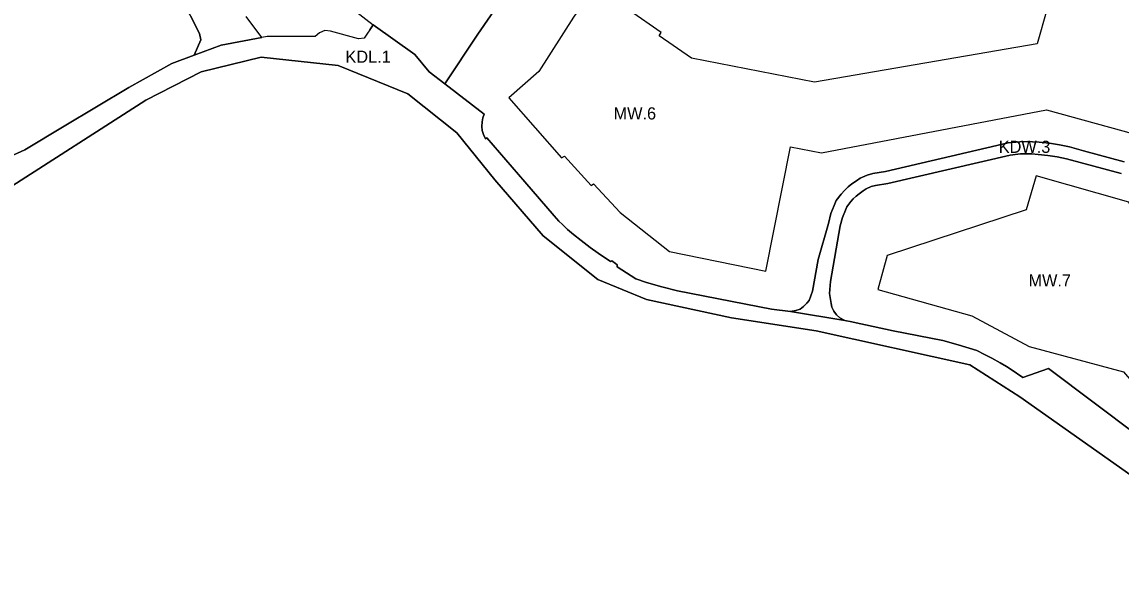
# Model space of a CAD drawing. Extents: x 7432050 to 7433361, y 5551438 to 5552391.
# Drawn here: x 7432631.9 to 7432993.3, y 5551479.7 to 5551658.9 of the extents above; entities that cross this region are included whole.
import ezdxf

# ---------------------------------------------------------------- set-up
doc = ezdxf.new("R2010")
doc.units = 0
for name, color, linetype in [('granica planu', 7, 'Continuous'), ('linie rozgraniczające', 7, 'Continuous'), ('nieprzekraczalne linie zabudowy', 7, 'Continuous'), ('oznaczenia przeznaczen', 7, 'Continuous')]:
    doc.layers.add(name, color=color, linetype=linetype)

msp = doc.modelspace()

# ---------------------------------------------------------------- linework, layer by layer
at = {"layer": 'granica planu'}
msp.add_line((7432710.59, 5551647.34), (7432690.81, 5551642.54), dxfattribs=at)
for points in [[(7432774.93, 5551622.43), (7432758.81, 5551635.29), (7432735.85, 5551644.65), (7432710.59, 5551647.34)], [(7432690.81, 5551642.54), (7432672.61, 5551633.22), (7432625.82, 5551603.17)], [(7432893.1, 5551557.41), (7432865.21, 5551561.71), (7432837.26, 5551567.72), (7432821.27, 5551574.22), (7432803.26, 5551588.64), (7432787.38, 5551607.01), (7432774.93, 5551622.43)], [(7433039.39, 5551479.73), (7432960, 5551535.68), (7432943.56, 5551546.17), (7432893.1, 5551557.41)]]:
    msp.add_lwpolyline(points, dxfattribs=at)
at = {"layer": 'linie rozgraniczające'}
for p, q in [((7432718.68, 5551680.18), (7432747.44, 5551658.04)), ((7432690.3, 5551655.18), (7432682.77, 5551670.1)), ((7432682.77, 5551670.1), (7432690.3, 5551655.18)), ((7432781.82, 5551654.95), (7432793.64, 5551672.05)), ((7432793.64, 5551672.05), (7432781.82, 5551654.95)), ((7432710.81, 5551653.82), (7432705.68, 5551660.68)), ((7432747.44, 5551658.04), (7432746.3, 5551656.38)), ((7432746.3, 5551656.38), (7432747.44, 5551658.04)), ((7432747.44, 5551658.04), (7432761.05, 5551648.27)), ((7432690.73, 5551653.11), (7432690.3, 5551655.18)), ((7432690.3, 5551655.18), (7432690.73, 5551653.11)), ((7432729.77, 5551655.4), (7432728.29, 5551654.19)), ((7432731.46, 5551656.08), (7432729.77, 5551655.4)), ((7432733.37, 5551655.91), (7432731.46, 5551656.08)), ((7432742.59, 5551653.39), (7432733.37, 5551655.91)), ((7432770.95, 5551638.61), (7432781.82, 5551654.95)), ((7432781.82, 5551654.95), (7432770.95, 5551638.61)), ((7432688.55, 5551648), (7432690.73, 5551653.11)), ((7432690.73, 5551653.11), (7432688.55, 5551648)), ((7432688.55, 5551648), (7432697.48, 5551651.33)), ((7432697.48, 5551651.33), (7432688.55, 5551648)), ((7432697.48, 5551651.33), (7432710.81, 5551653.82)), ((7432727.9, 5551654.19), (7432712.5, 5551654.14)), ((7432728.29, 5551654.19), (7432727.9, 5551654.19)), ((7432744.43, 5551653.65), (7432742.59, 5551653.39)), ((7432681.19, 5551645.26), (7432688.55, 5551648)), ((7432688.55, 5551648), (7432681.19, 5551645.26)), ((7432690.81, 5551642.54), (7432710.59, 5551647.34)), ((7432710.59, 5551647.34), (7432690.81, 5551642.54)), ((7432710.59, 5551647.34), (7432735.85, 5551644.65)), ((7432761.05, 5551648.27), (7432765.76, 5551642.57)), ((7432667.11, 5551637.34), (7432681.19, 5551645.26)), ((7432735.85, 5551644.65), (7432758.81, 5551635.29)), ((7432672.61, 5551633.22), (7432690.81, 5551642.54)), ((7432765.76, 5551642.57), (7432770.95, 5551638.61)), ((7432645.84, 5551624.65), (7432667.11, 5551637.34)), ((7432625.82, 5551603.17), (7432672.61, 5551633.22)), ((7432758.81, 5551635.29), (7432774.93, 5551622.43)), ((7432774.93, 5551622.43), (7432787.38, 5551607.01)), ((7432783.67, 5551621.94), (7432784.29, 5551620.49)), ((7432784.29, 5551620.49), (7432783.67, 5551621.94)), ((7432784.29, 5551620.49), (7432784.8, 5551620.82)), ((7432784.8, 5551620.82), (7432784.29, 5551620.49)), ((7432784.8, 5551620.82), (7432797.25, 5551606.4)), ((7432797.25, 5551606.4), (7432784.8, 5551620.82)), ((7432966.39, 5551619.39), (7432964.19, 5551619.57)), ((7432976.35, 5551617.83), (7432973.03, 5551618.54)), ((7432949.18, 5551617.52), (7432915.83, 5551609.78)), ((7432956.82, 5551615.19), (7432916.62, 5551605.86)), ((7432916.62, 5551605.86), (7432956.82, 5551615.19)), ((7432960.22, 5551615.53), (7432956.82, 5551615.19)), ((7432956.82, 5551615.19), (7432960.22, 5551615.53)), ((7432962.4, 5551615.6), (7432960.22, 5551615.53)), ((7432960.22, 5551615.53), (7432962.4, 5551615.6)), ((7432963.98, 5551615.57), (7432962.4, 5551615.6)), ((7432962.4, 5551615.6), (7432963.98, 5551615.57)), ((7432966.02, 5551615.4), (7432963.98, 5551615.57)), ((7432963.98, 5551615.57), (7432966.02, 5551615.4)), ((7432969.23, 5551615.07), (7432966.02, 5551615.4)), ((7432966.02, 5551615.4), (7432969.23, 5551615.07)), ((7432972.31, 5551614.61), (7432969.23, 5551615.07)), ((7432969.23, 5551615.07), (7432972.31, 5551614.61)), ((7432975.4, 5551613.94), (7432972.31, 5551614.61)), ((7432972.31, 5551614.61), (7432975.4, 5551613.94)), ((7432980.9, 5551616.6), (7432976.35, 5551617.83)), ((7432994.34, 5551612.91), (7432980.9, 5551616.6)), ((7432979.85, 5551612.74), (7432975.4, 5551613.94)), ((7432975.4, 5551613.94), (7432979.85, 5551612.74)), ((7432993.28, 5551609.06), (7432979.85, 5551612.74)), ((7432979.85, 5551612.74), (7432993.28, 5551609.06)), ((7432907.55, 5551607.55), (7432906.3, 5551606.7)), ((7432909.78, 5551608.57), (7432907.55, 5551607.55)), ((7432911.68, 5551609.06), (7432909.78, 5551608.57)), ((7432915.83, 5551609.78), (7432911.68, 5551609.06)), ((7432787.38, 5551607.01), (7432803.26, 5551588.64)), ((7432797.25, 5551606.4), (7432806.89, 5551595.14)), ((7432806.89, 5551595.14), (7432797.25, 5551606.4)), ((7432909.53, 5551604.05), (7432908.55, 5551603.39)), ((7432908.55, 5551603.39), (7432909.53, 5551604.05)), ((7432911.13, 5551604.79), (7432909.53, 5551604.05)), ((7432909.53, 5551604.05), (7432911.13, 5551604.79)), ((7432912.53, 5551605.15), (7432911.13, 5551604.79)), ((7432911.13, 5551604.79), (7432912.53, 5551605.15)), ((7432916.62, 5551605.86), (7432912.53, 5551605.15)), ((7432912.53, 5551605.15), (7432916.62, 5551605.86)), ((7432901.31, 5551602.35), (7432899.67, 5551600.18)), ((7432905.21, 5551600.76), (7432904.43, 5551599.85)), ((7432904.43, 5551599.85), (7432905.21, 5551600.76)), ((7432906.18, 5551601.66), (7432905.21, 5551600.76)), ((7432905.21, 5551600.76), (7432906.18, 5551601.66)), ((7432907.16, 5551602.45), (7432906.18, 5551601.66)), ((7432906.18, 5551601.66), (7432907.16, 5551602.45)), ((7432908.55, 5551603.39), (7432907.16, 5551602.45)), ((7432907.16, 5551602.45), (7432908.55, 5551603.39)), ((7432902.64, 5551597.04), (7432901.67, 5551594.67)), ((7432901.67, 5551594.67), (7432902.64, 5551597.04)), ((7432903.13, 5551598.12), (7432902.64, 5551597.04)), ((7432902.64, 5551597.04), (7432903.13, 5551598.12)), ((7432904.43, 5551599.85), (7432903.13, 5551598.12)), ((7432903.13, 5551598.12), (7432904.43, 5551599.85)), ((7432897.85, 5551595.92), (7432897.06, 5551592.7)), ((7432901.67, 5551594.67), (7432900.98, 5551591.88)), ((7432900.98, 5551591.88), (7432901.67, 5551594.67)), ((7432897.06, 5551592.7), (7432893.69, 5551580.78)), ((7432900.98, 5551591.88), (7432897.71, 5551573.62)), ((7432897.71, 5551573.62), (7432900.98, 5551591.88)), ((7432803.26, 5551588.64), (7432821.27, 5551574.22)), ((7432818.75, 5551584.81), (7432821.43, 5551582.88)), ((7432821.43, 5551582.88), (7432818.75, 5551584.81)), ((7432821.43, 5551582.88), (7432825.46, 5551580.23)), ((7432825.46, 5551580.23), (7432821.43, 5551582.88)), ((7432827.03, 5551579.49), (7432827.61, 5551579.04)), ((7432827.61, 5551579.04), (7432827.03, 5551579.49)), ((7432821.27, 5551574.22), (7432837.26, 5551567.72)), ((7432833.8, 5551574.53), (7432837.32, 5551573.28)), ((7432837.32, 5551573.28), (7432833.8, 5551574.53)), ((7432837.32, 5551573.28), (7432842.27, 5551571.82)), ((7432842.27, 5551571.82), (7432837.32, 5551573.28)), ((7432842.27, 5551571.82), (7432847.51, 5551570.56)), ((7432847.51, 5551570.56), (7432842.27, 5551571.82)), ((7432897.4, 5551569.62), (7432897.71, 5551573.62)), ((7432898, 5551566.33), (7432897.4, 5551569.62)), ((7432886.35, 5551564.02), (7432884.58, 5551563.76)), ((7432887.75, 5551564.47), (7432886.35, 5551564.02)), ((7432888.9, 5551565.33), (7432887.75, 5551564.47)), ((7432889.99, 5551566.48), (7432888.9, 5551565.33)), ((7432890.78, 5551567.38), (7432889.99, 5551566.48)), ((7432884.58, 5551563.76), (7432902.52, 5551560.82)), ((7432902.52, 5551560.82), (7432904.79, 5551560.32)), ((7432893.1, 5551557.41), (7432943.56, 5551546.17)), ((7432904.79, 5551560.32), (7432905.22, 5551560.23)), ((7432905.22, 5551560.23), (7432904.79, 5551560.32)), ((7432945.89, 5551550.91), (7432948.43, 5551549.61)), ((7432948.43, 5551549.61), (7432945.89, 5551550.91))]:
    msp.add_line(p, q, dxfattribs=at)
for points in [[(7432761.05, 5551648.27), (7432747.44, 5551658.04), (7432744.43, 5551653.65)], [(7432712.5, 5551654.14), (7432710.81, 5551653.82), (7432697.48, 5551651.33)], [(7432774.93, 5551622.43), (7432758.81, 5551635.29), (7432735.85, 5551644.65), (7432710.59, 5551647.34)], [(7432770.95, 5551638.61), (7432765.76, 5551642.57), (7432761.05, 5551648.27)], [(7432681.19, 5551645.26), (7432667.11, 5551637.34), (7432645.84, 5551624.65)], [(7432690.81, 5551642.54), (7432672.61, 5551633.22), (7432625.82, 5551603.17)], [(7432770.95, 5551638.61), (7432783.88, 5551628.57), (7432783.47, 5551627.38)], [(7432783.47, 5551627.38), (7432783.88, 5551628.57), (7432770.95, 5551638.61)], [(7432783.47, 5551627.38), (7432783.19, 5551626.14), (7432783.08, 5551624.53)], [(7432783.08, 5551624.53), (7432783.19, 5551626.14), (7432783.47, 5551627.38)], [(7432645.84, 5551624.65), (7432632.85, 5551616.9), (7432621.14, 5551611.65), (7432612.02, 5551610.41), (7432589.83, 5551610.6)], [(7432621.14, 5551611.65), (7432632.85, 5551616.9), (7432645.84, 5551624.65)], [(7432893.1, 5551557.41), (7432865.21, 5551561.71), (7432837.26, 5551567.72), (7432821.27, 5551574.22), (7432803.26, 5551588.64), (7432787.38, 5551607.01), (7432774.93, 5551622.43)], [(7432783.08, 5551624.53), (7432783.27, 5551623.24), (7432783.67, 5551621.94)], [(7432783.67, 5551621.94), (7432783.27, 5551623.24), (7432783.08, 5551624.53)], [(7432884.58, 5551563.76), (7432886.35, 5551564.02), (7432887.75, 5551564.47), (7432888.9, 5551565.33), (7432889.99, 5551566.48), (7432890.78, 5551567.38), (7432891.8, 5551570.42), (7432893.69, 5551580.78), (7432897.06, 5551592.7), (7432897.85, 5551595.92), (7432898.97, 5551598.63), (7432899.67, 5551600.18), (7432901.31, 5551602.35), (7432902.32, 5551603.53), (7432903.56, 5551604.69), (7432904.78, 5551605.67), (7432906.3, 5551606.7), (7432907.55, 5551607.55), (7432909.78, 5551608.57), (7432911.68, 5551609.06), (7432915.83, 5551609.78), (7432949.18, 5551617.52), (7432956.17, 5551619.14)], [(7432959.96, 5551619.52), (7432956.17, 5551619.14), (7432949.18, 5551617.52)], [(7432956.17, 5551619.14), (7432959.96, 5551619.52), (7432962.38, 5551619.6), (7432964.19, 5551619.57), (7432966.39, 5551619.39), (7432969.73, 5551619.04), (7432973.03, 5551618.54), (7432976.35, 5551617.83), (7432980.9, 5551616.6), (7432994.34, 5551612.91)], [(7432964.19, 5551619.57), (7432962.38, 5551619.6), (7432959.96, 5551619.52)], [(7432973.03, 5551618.54), (7432969.73, 5551619.04), (7432966.39, 5551619.39)], [(7432903.56, 5551604.69), (7432902.32, 5551603.53), (7432901.31, 5551602.35)], [(7432906.3, 5551606.7), (7432904.78, 5551605.67), (7432903.56, 5551604.69)], [(7432899.67, 5551600.18), (7432898.97, 5551598.63), (7432897.85, 5551595.92)], [(7432806.89, 5551595.14), (7432808.4, 5551593.4), (7432809.68, 5551592.3), (7432811.33, 5551590.72), (7432813.31, 5551589.1), (7432815.82, 5551587.03), (7432818.75, 5551584.81)], [(7432818.75, 5551584.81), (7432815.82, 5551587.03), (7432813.31, 5551589.1), (7432811.33, 5551590.72), (7432809.68, 5551592.3), (7432808.4, 5551593.4), (7432806.89, 5551595.14)], [(7432825.46, 5551580.23), (7432825.84, 5551580.43), (7432827.03, 5551579.49)], [(7432827.03, 5551579.49), (7432825.84, 5551580.43), (7432825.46, 5551580.23)], [(7432827.61, 5551579.04), (7432827.59, 5551578.4), (7432833.8, 5551574.53)], [(7432833.8, 5551574.53), (7432827.59, 5551578.4), (7432827.61, 5551579.04)], [(7432893.69, 5551580.78), (7432891.8, 5551570.42), (7432890.78, 5551567.38)], [(7432897.71, 5551573.62), (7432897.4, 5551569.62), (7432898, 5551566.33), (7432898.21, 5551565.16), (7432898.83, 5551563.85), (7432899.76, 5551562.68), (7432900.81, 5551561.66), (7432902.52, 5551560.82)], [(7432837.26, 5551567.72), (7432865.21, 5551561.71), (7432893.1, 5551557.41)], [(7432847.51, 5551570.56), (7432878.38, 5551564.52), (7432884.58, 5551563.76)], [(7432904.79, 5551560.32), (7432902.52, 5551560.82), (7432884.58, 5551563.76), (7432878.38, 5551564.52), (7432847.51, 5551570.56)], [(7432902.52, 5551560.82), (7432900.81, 5551561.66), (7432899.76, 5551562.68), (7432898.83, 5551563.85), (7432898.21, 5551565.16), (7432898, 5551566.33)], [(7433039.39, 5551479.73), (7432960, 5551535.68), (7432943.56, 5551546.17), (7432893.1, 5551557.41)], [(7432905.22, 5551560.23), (7432918.37, 5551557.41), (7432934.71, 5551554.24)], [(7432934.71, 5551554.24), (7432918.37, 5551557.41), (7432905.22, 5551560.23)], [(7432934.71, 5551554.24), (7432939.72, 5551552.83), (7432945.89, 5551550.91)], [(7432945.89, 5551550.91), (7432939.72, 5551552.83), (7432934.71, 5551554.24)], [(7432948.43, 5551549.61), (7432950.83, 5551548.4), (7432953.57, 5551546.87), (7432955.65, 5551545.63), (7432957.13, 5551544.64)], [(7432957.13, 5551544.64), (7432955.65, 5551545.63), (7432953.57, 5551546.87), (7432950.83, 5551548.4), (7432948.43, 5551549.61)], [(7432943.56, 5551546.17), (7432960, 5551535.68), (7433039.39, 5551479.73)], [(7432957.13, 5551544.64), (7432960.96, 5551542.08), (7432969.46, 5551544.99), (7432999.04, 5551522.76)], [(7432999.04, 5551522.76), (7432969.46, 5551544.99), (7432960.96, 5551542.08), (7432957.13, 5551544.64)]]:
    msp.add_lwpolyline(points, dxfattribs=at)
at = {"layer": 'nieprzekraczalne linie zabudowy'}
msp.add_line((7432968.76, 5551630.02), (7433009.24, 5551618.85), dxfattribs=at)
for points in [[(7432968.59, 5551679.75), (7432968.91, 5551662.87), (7432965.67, 5551651.72), (7432892.55, 5551639.17)], [(7432892.55, 5551639.17), (7432852.08, 5551647.07), (7432841.41, 5551654.32), (7432842.1, 5551655.45), (7432831.65, 5551662.69), (7432832.27, 5551663.62), (7432820.84, 5551671.53), (7432813.24, 5551660.54), (7432801.85, 5551642.62), (7432792.04, 5551633.94), (7432809.37, 5551614.23), (7432810.26, 5551614.85), (7432819.05, 5551605.16), (7432819.83, 5551605.73), (7432828.62, 5551596.32), (7432844.86, 5551583.49), (7432876.55, 5551576.98), (7432884.62, 5551617.91), (7432894.81, 5551615.85), (7432968.76, 5551630.02)]]:
    msp.add_lwpolyline(points, dxfattribs=at)
msp.add_lwpolyline([(7432913.28, 5551570.92), (7432944.25, 5551562.35), (7432963.1, 5551552.22), (7432994.07, 5551543.89), (7433009.28, 5551526.25), (7433007.73, 5551520.67), (7433038.85, 5551512.28), (7433040.78, 5551511.76), (7433043.99, 5551523.99), (7433039.6, 5551557.15), (7433042.76, 5551567.67), (7433042.94, 5551568.29), (7433040.67, 5551568.91), (7433009.86, 5551577.26), (7432995.86, 5551599.73), (7432965.34, 5551608.36), (7432962.07, 5551597.14), (7432916.36, 5551582.2)], close=True, dxfattribs=at)

# ---------------------------------------------------------------- texts
at = {"layer": 'oznaczenia przeznaczen'}
for s, p in [('KDL.1', (7432738.3, 5551645.5)), ('MW.6', (7432826.45, 5551626.87)), ('KDW.3', (7432953.09, 5551615.89)), ('MW.7', (7432962.86, 5551571.96))]:
    msp.add_text(s, height=4, dxfattribs=at).set_placement(p)

doc.saveas('drawing.dxf')
